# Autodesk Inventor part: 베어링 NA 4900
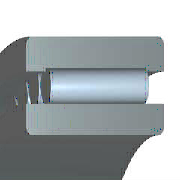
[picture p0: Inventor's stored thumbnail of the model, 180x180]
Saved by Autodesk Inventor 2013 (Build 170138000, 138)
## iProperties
Created: 2009-02
Part Number: 베어링 NA 4900
Material: 스테인리스강
Description: 니들 롤러 베어링 - 경계 치수 및 공차
Document SubType Name: Modeling
Standard: KS B 2029
Designer: SeoGD™
Standards Organization: KS
Language: ko-KR
Size Designation: NA 4900 - 10 x 22 x 13
Categories: <MemberInstance><Categories><Category DisplayName="샤프트 부품" InternalName="7f7aeb1f-a693-4053-b835-cee3144e0d98" Mnemonic="SHFT"><Category DisplayName="베어링" Inter
Density: 8.08 g/cm^3
Mass: 24.4881 g
Surface Area: 38.613 cm^2
Volume: 3.03071 cm^3
IsCustomPart: 0
Author: SeoGD™
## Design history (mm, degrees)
sketch "스케치"
  geometry: L1 (1.857, 9)-(11.143, 9); L2 (11.143, 9)-(11.143, 7); L3 (13, 7)-(0, 7); L4 (1.857, 7)-(1.857, 9); L5 (1.857, 8)-(11.143, 8); L6 (6.5, 8)-(6.5, 7); L7 (0, 5)-(13, 5); L8 (0, 11)-(13, 11); L9 (13, 5)-(13, 7); L10 (13, 8.8)-(13, 11); L11 (1.857, 8.8)-(0, 8.8); L12 (11.143, 8.8)-(13, 8.8); L13 (-6, 0)-(36, 0) reference; L14 (0, -1.9)-(0, 14.9) reference
  constraints: 24 end point, 8 point on line, 3 midpoint, 3 parallel, 3 perpendicular, 2 symmetric about line, 1 horizontal, 1 other
  dimensions: "d6" = 10 diameter of L7 L13 (= WD); "d7" = 14 diameter of L3 L13 (= KID1); "d8" = 22 diameter of L8 L13 (= BD); "d9" = 16 diameter of L6.start L13 (= 0.5 x WD + 0.5 x BD); "d10" = 17.6 diameter of L12 L13 (= 0.9 x BD + 0.9 x WD - 0.8 x KID1); "d11" = 18 diameter of L1 L13 (= BD + WD - KID1); "d12" = 1.85714 distance between parallel lines of L14 L4 (= 0.142857 x KB); "d13" = 13 distance between parallel lines of L14 L9 (= KB); "d14" = 11.14286 distance between parallel lines of L14 L2 (= 0.857143 x KB)
revolve "본체" stored, may be unused: angle "d17" = 90 deg
revolve "롤러" stored, may be unused: angle "d18" = 90 deg
pattern_circular "IDS_ARRAYROLLER[SIMPL:T]" dims angle "d2" = 360 deg
body "Solid1"
fillet "모깎기1" dims "d0" = 0.3 (= KRS)
other parameters: "WD" = 10 [user parameter; used in 6 equation terms], "BD" = 22 [user parameter; used in 6 equation terms], "KB" = 13 [user parameter; used in 3 equation terms], "KID1" = 14 [user parameter; used in 4 equation terms], "KRS" = 0.3 [user parameter; used in 1 equation term], "d3" = 0, "d4" = 0, "d5" = 0, "d15" = 0, "d16" = 0, "BC0" = 9150000 [user parameter], "WR" = 5 (= 0.5 x WD) [user parameter], "BBA" = 0 [user parameter], "BC" = 8150000 [user parameter], "BR" = 11 (= 0.5 x BD) [user parameter]
